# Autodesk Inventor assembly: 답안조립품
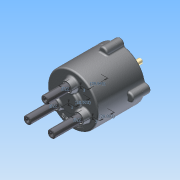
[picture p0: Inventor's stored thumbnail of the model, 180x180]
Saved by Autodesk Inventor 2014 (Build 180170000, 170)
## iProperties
Created: 2015-09
Part Number: 답안조립품
Document SubType Name: Assembly
Designer: study
Mass: 2160.28 g
Surface Area: 1801.23 cm^2
Volume: 438.526 cm^3
Density: 4.92622 g/cm^3
Author: study
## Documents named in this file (14)
- C:\Users\study\Desktop\350916V1007\답안조립품.iam
- C:\Users\study\Desktop\350916V1007\몸체.ipt
- C:\Users\study\Desktop\350916V1007\멈춤링 10 x 1.ipt
- C:\Users\study\Desktop\350916V1007\멈춤링 22 x 1.2.ipt
- C:\Users\study\Desktop\350916V1007\메인 축.ipt
- C:\Users\study\Desktop\350916V1007\베어링 NA 4900.ipt
- C:\Users\study\Desktop\350916V1007\판캠.ipt
- C:\Users\study\Desktop\350916V1007\M5x0.8x20.ipt
- C:\Users\study\Desktop\350916V1007\오일실.ipt
- C:\Users\study\Desktop\350916V1007\커버.ipt
- C:\Users\study\Desktop\350916V1007\슬라이드 축.ipt
- C:\Users\study\Desktop\350916V1007\11-가변스프링.ipt
- C:\Users\study\Desktop\350916V1007\12-가변스프링.ipt
- C:\Users\study\Desktop\350916V1007\13-가변스프링.ipt
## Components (7 placed, 4 different names)
1. 11-가변스프링:1
2. 12-가변스프링:1
3. 13-가변스프링:1
4. M5x0.8x20:1
5. M5x0.8x20:2
6. M5x0.8x20:3
7. M5x0.8x20:4
